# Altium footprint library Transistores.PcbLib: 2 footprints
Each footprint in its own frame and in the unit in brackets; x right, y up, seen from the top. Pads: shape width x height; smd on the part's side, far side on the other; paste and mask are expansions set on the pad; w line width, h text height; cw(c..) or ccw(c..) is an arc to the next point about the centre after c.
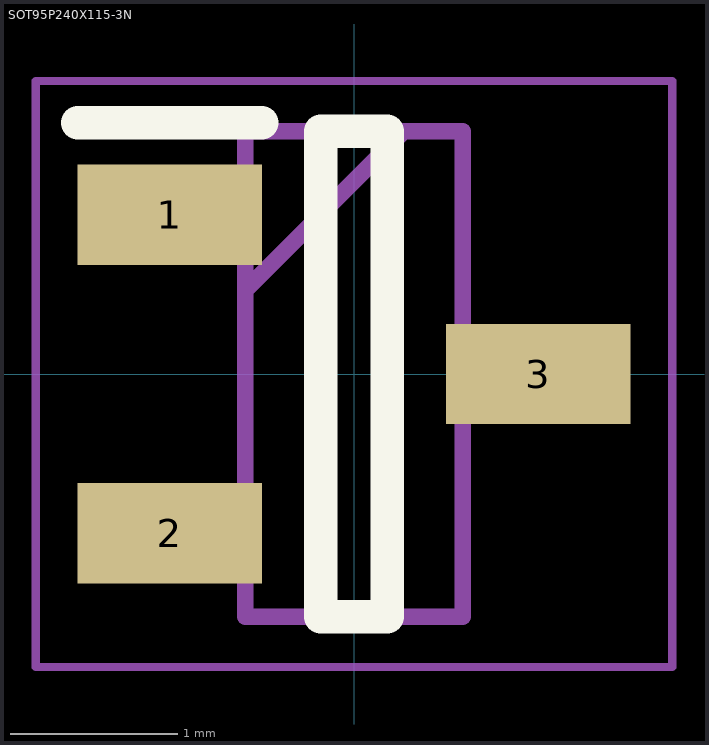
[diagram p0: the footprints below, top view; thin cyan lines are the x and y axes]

## PCBComponent_1 [mm]

## SOT95P240X115-3N [mm]
pads (3):
  rect 1.1x0.6 smd: 1(-1.1,0.95) 2(-1.1,-0.95) 3(1.1,0)
Top Overlay:
  lines w0.2: -1.65,1.5 -0.55,1.5 ; -0.2,-1.45 -0.2,1.45 0.2,1.45 0.2,-1.45 -0.2,-1.45
Mechanical 13:
  lines w0.1: -0.65,0.5 0.3,1.45 ; -0.65,-1.45 -0.65,1.45 0.65,1.45 0.65,-1.45 -0.65,-1.45
Mechanical 15:
  lines w0.05: -1.9,-1.75 -1.9,1.75 1.9,1.75 1.9,-1.75 -1.9,-1.75
3D body "SS8050-G.stp": height 1.15, standoff 0, extent -1.2,-1.45 1.2,1.45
